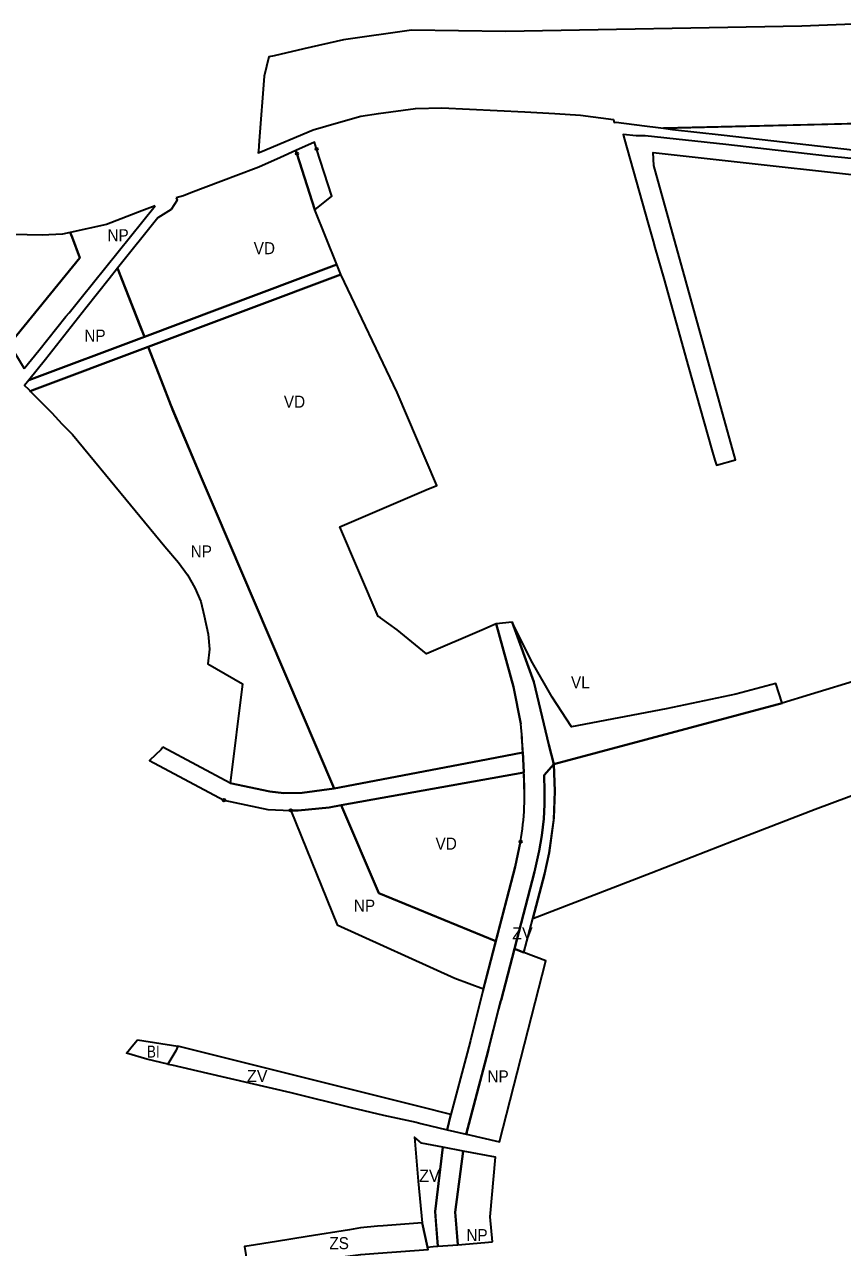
# Model space of a CAD drawing. Extents: x -650276 to -642489, y -1074311 to -1066658.
# Drawn here: x -649555 to -648741, y -1070383 to -1069166 of the extents above; entities that cross this region are included whole.
import ezdxf

# ---------------------------------------------------------------- set-up
doc = ezdxf.new("R2010")
doc.units = 0
doc.header["$LTSCALE"] = 4.8
doc.header["$PDMODE"] = 32
doc.header["$PDSIZE"] = 2.4
for name, color, linetype, lineweight in [('13', 7, 'Continuous', 35), ('15', 7, 'Continuous', 35), ('2', 7, 'Continuous', 35), ('24', 7, 'Continuous', 35), ('25', 7, 'Continuous', 35), ('35', 7, 'Continuous', 35), ('40', 7, 'Continuous', 35), ('41', 7, 'Continuous', 35), ('48', 7, 'Continuous', 35)]:
    doc.layers.add(name, color=color, linetype=linetype, lineweight=lineweight)
doc.layers.add('62', color=7, linetype='Continuous')

msp = doc.modelspace()

# ---------------------------------------------------------------- linework, layer by layer
at = {"layer": '13'}
msp.add_lwpolyline([(-648722.24, -1069817.54), (-648772.48, -1069832.83), (-648800.85, -1069841.52), (-649028.017, -1069902.109), (-649027.135, -1069928.902), (-649027.953, -1069955.702), (-649032.644, -1069990.371), (-649037.411, -1070011.659), (-649048.918, -1070055.852), (-648931.057, -1070010.171), (-648849.532, -1069978.559), (-648767.83, -1069946.87), (-648562.242, -1069870.301)], dxfattribs=at)
at = {"layer": '15'}
msp.add_line((-649057.868, -1069910.51), (-649058.82, -1069890.548), dxfattribs=at)
for points in [[(-648725.82, -1069299.81), (-648741.58, -1069298.16), (-648755.56, -1069296.7), (-648856.68, -1069285.01), (-648937.2, -1069276.37), (-648945.96, -1069276.64), (-648959.11, -1069275.13), (-648957.74, -1069280), (-648934.38, -1069362.79), (-648929.16, -1069381.32), (-648927.37, -1069387.62), (-648927.38, -1069387.623), (-648918.65, -1069418.53), (-648893.86, -1069506.89), (-648870.76, -1069589.26), (-648867.62, -1069599.37), (-648866.17, -1069604.48), (-648847.097, -1069598.995), (-648928.347, -1069306.125), (-648929.112, -1069293.123), (-648642.241, -1069324.949)], [(-649431.761, -1069486.57), (-649240.202, -1069414.528), (-649244.08, -1069404.753), (-649435.578, -1069476.772), (-649550.53, -1069519.68)], [(-649548.881, -1069530.963), (-649547.733, -1069530.185), (-649431.761, -1069486.57)], [(-649550.53, -1069519.68), (-649554.83, -1069525), (-649551.32, -1069528.49), (-649549.69, -1069530.14), (-649548.881, -1069530.963)], [(-649029.61, -1069835.47), (-649049.22, -1069801.23), (-649058.34, -1069783.72), (-649069.4, -1069760.67)], [(-649069.4, -1069760.67), (-649048, -1069820), (-649032.928, -1069882.782)], [(-649032.928, -1069882.782), (-649028.017, -1069902.109), (-648800.85, -1069841.52), (-648806.946, -1069821.79), (-648846.939, -1069832.584), (-648846.94, -1069832.584)], [(-648846.94, -1069832.584), (-648916.03, -1069847.12), (-649010.55, -1069865.09), (-649029.61, -1069835.47)], [(-649417.234, -1069885.193), (-649418.94, -1069887.36), (-649430.515, -1069898.514), (-649356.458, -1069937.945)], [(-649246.81, -1069926.27), (-649278.492, -1069930.573), (-649296.851, -1069931.092), (-649310.738, -1069929.342), (-649350.222, -1069920.873), (-649417.234, -1069885.193)], [(-649058.82, -1069890.548), (-649101.89, -1069898.73), (-649246.81, -1069926.27)], [(-649289.95, -1069948.146), (-649282.437, -1069948.342), (-649251.805, -1069945.276), (-649239.635, -1069943.094), (-649057.868, -1069910.51)], [(-649356.458, -1069937.945), (-649312.646, -1069947.342), (-649289.95, -1069948.146)]]:
    msp.add_lwpolyline(points, dxfattribs=at)
for p in [(-649356.458, -1069937.945), (-649289.95, -1069948.146)]:
    msp.add_point(p, dxfattribs=at)
at = {"layer": '2'}
msp.add_lwpolyline([(-649442.63, -1070176.69), (-649402.29, -1070182.92), (-649404.2, -1070187.43), (-649412.2, -1070200.71), (-649433.3, -1070195.89), (-649453.27, -1070190.02), (-649446.19, -1070180.76)], close=True, dxfattribs=at)
at = {"layer": '24'}
for p, q in [((-649283.702, -1069294.132), (-649265.774, -1069350.068)), ((-649058.858, -1069889.759), (-649057.868, -1069910.51)), ((-649057.134, -1069932.873), (-649057.868, -1069910.51)), ((-649146.163, -1070347.543), (-649145.424, -1070357.637))]:
    msp.add_line(p, q, dxfattribs=at)
for points in [[(-648721.315, -1069164.952), (-648781.015, -1069167.44), (-649076.02, -1069172.683), (-649169.781, -1069171.432), (-649237.512, -1069180.731), (-649277.021, -1069189.913), (-649306.455, -1069196.754), (-649311.633, -1069197.958), (-649316.47, -1069216.91), (-649321.32, -1069281.47), (-649322.09, -1069291.73), (-649322.22, -1069293.54), (-649319.72, -1069292.47), (-649267.5, -1069270.41), (-649242.5, -1069263.3), (-649220.18, -1069257.03), (-649202.63, -1069254.4), (-649165.62, -1069249.43), (-649139.63, -1069248.73), (-649056.95, -1069252.55), (-649026.955, -1069254.366), (-649001.3, -1069255.92), (-648968.49, -1069260.36), (-648968.05, -1069263.06), (-648965.8, -1069262.75), (-648937.91, -1069266.51), (-648924.13, -1069268.21), (-648918.889, -1069268.875), (-648673.267, -1069262.895)], [(-649264.156, -1069289.589), (-649266.331, -1069282.804), (-649284.695, -1069291.033), (-649283.702, -1069294.132)], [(-649265.774, -1069350.068), (-649249.069, -1069336.66), (-649264.156, -1069289.589)], [(-649061.138, -1069979.243), (-649061.138, -1069979.243), (-649061.139, -1069979.254), (-649066.487, -1070004.267), (-649098.65, -1070127.795), (-649110.925, -1070177.113), (-649114.174, -1070189.816), (-649130.712, -1070250.935), (-649134.294, -1070266.095), (-649115.159, -1070270.568), (-649095.152, -1070193.731), (-649093.095, -1070186.132), (-649095.152, -1070193.731), (-649080.924, -1070137.409), (-649080.38, -1070136.996), (-649047.131, -1070009.304), (-649042.468, -1069988.477), (-649042.468, -1069988.477), (-649039.966, -1069973.035), (-649037.98, -1069956.626), (-649037.322, -1069942.129), (-649037.137, -1069928.996), (-649037.665, -1069912.977), (-649028.017, -1069902.109), (-649032.928, -1069882.782), (-649048, -1069820), (-649069.4, -1069760.67), (-649085.41, -1069762.44), (-649068, -1069825.147), (-649060.897, -1069861.994)], [(-649138.43, -1070283.6), (-649146.163, -1070347.543), (-649146.163, -1070347.543), (-649145.424, -1070357.637)], [(-649125.503, -1070355.837), (-649126.069, -1070348.097), (-649118.257, -1070287.455), (-649138.43, -1070283.6), (-649146.163, -1070347.543)], [(-649125.503, -1070355.837), (-649126.069, -1070348.097), (-649118.257, -1070287.455), (-649138.43, -1070283.6)], [(-649145.424, -1070357.637), (-649143.633, -1070382.123), (-649123.693, -1070380.572), (-649125.503, -1070355.837)], [(-649145.424, -1070357.637), (-649143.633, -1070382.123), (-649123.693, -1070380.572), (-649125.503, -1070355.837)]]:
    msp.add_lwpolyline(points, dxfattribs=at)
for centre, radius, start, end in [((-649633.43, -1069918.001), 575.266, 2.81398, 5.58706), ((-649347.129, -1069931.193), 290, 350.46253, 4.08974), ((-649347.129, -1069931.193), 290, 359.66809, 4.08974)]:
    msp.add_arc(centre, radius, start, end, dxfattribs=at)
for p in [(-649264.156, -1069289.589), (-649283.702, -1069294.132)]:
    msp.add_point(p, dxfattribs=at)
at = {"layer": '25'}
msp.add_lwpolyline([(-648730.66, -1069290.43), (-648656.242, -1069297.116), (-648673.267, -1069262.895), (-648761.189, -1069265.035), (-648918.889, -1069268.875), (-648909.86, -1069270.02), (-648861.49, -1069275.34), (-648785.92, -1069284.2), (-648730.66, -1069290.43)], close=True, dxfattribs=at)
at = {"layer": '35'}
msp.add_line((-649202.375, -1070030.469), (-649085.737, -1070078.201), dxfattribs=at)
for points in [[(-649283.702, -1069294.132), (-649284.695, -1069291.033), (-649300.133, -1069297.95), (-649321.69, -1069307.61)], [(-649244.08, -1069404.753), (-649265.774, -1069350.068), (-649283.702, -1069294.132)], [(-649321.69, -1069307.61), (-649324.3, -1069308.59), (-649359.48, -1069321.82), (-649389.4, -1069333.35), (-649396.52, -1069336.09), (-649403.92, -1069338.26)], [(-649403.92, -1069338.26), (-649403.03, -1069340.66), (-649408.81, -1069349.89), (-649422.19, -1069357.99), (-649462.25, -1069408.32), (-649435.578, -1069476.772), (-649244.08, -1069404.753)], [(-649060.897, -1069861.994), (-649068, -1069825.147), (-649085.41, -1069762.44), (-649085.41, -1069762.44), (-649099.75, -1069768.575), (-649154.76, -1069792.11), (-649184.05, -1069768.45), (-649200.64, -1069756.53), (-649202.99, -1069754.99), (-649241.11, -1069665.9), (-649155.082, -1069629.097), (-649144.57, -1069624.6), (-649184.1, -1069532.2), (-649240.202, -1069414.528), (-649431.761, -1069486.57), (-649416.52, -1069525.68), (-649409.355, -1069544.517), (-649388.438, -1069594.296), (-649379.32, -1069615.71), (-649364.44, -1069650.55), (-649312.03, -1069773.33)], [(-649312.03, -1069773.33), (-649246.81, -1069926.27), (-649101.89, -1069898.73), (-649058.82, -1069890.548)], [(-649057.868, -1069910.51), (-649239.635, -1069943.094), (-649202.375, -1070030.469)], [(-649085.737, -1070078.201), (-649066.487, -1070004.267), (-649061.139, -1069979.254), (-649061.138, -1069979.243)]]:
    msp.add_lwpolyline(points, dxfattribs=at)
for centre, radius, start, end in [((-649649.71, -1069919.176), 591.583, 2.77379, 5.54687), ((-649347.129, -1069931.193), 290, 350.46253, 4.08974)]:
    msp.add_arc(centre, radius, start, end, dxfattribs=at)
msp.add_point((-649061.138, -1069979.243), dxfattribs=at)
at = {"layer": '40'}
for points in [[(-649060.411, -1070060.306), (-649067.061, -1070085.844), (-649057.722, -1070089.665), (-649048.918, -1070055.852), (-649037.411, -1070011.659), (-649032.644, -1069990.371), (-649028.007, -1069957.455), (-649027.135, -1069928.902), (-649028.017, -1069902.109), (-649037.665, -1069912.977), (-649037.137, -1069928.996), (-649037.322, -1069942.129), (-649037.98, -1069956.626), (-649039.966, -1069973.035), (-649042.468, -1069988.477), (-649047.131, -1070009.304)], [(-649160.748, -1070243.413), (-649402.29, -1070182.92), (-649404.2, -1070187.43), (-649412.2, -1070200.71), (-649412.2, -1070200.71), (-649408.24, -1070201.62), (-649372.69, -1070209.74), (-649289.83, -1070229.16), (-649229.8, -1070243.94), (-649197.55, -1070251.65), (-649164.91, -1070258.55), (-649160.54, -1070259.96), (-649134.294, -1070266.095), (-649130.712, -1070250.935)], [(-649138.43, -1070283.6), (-649159.78, -1070279.52), (-649166.86, -1070273.48), (-649162.91, -1070317.47), (-649159.19, -1070358.82), (-649153.64, -1070382.9), (-649148.23, -1070382.48), (-649143.633, -1070382.123), (-649146.163, -1070347.543)]]:
    msp.add_lwpolyline(points, close=True, dxfattribs=at)
at = {"layer": '41'}
msp.add_lwpolyline([(-649570.03, -1069483.83), (-649499.761, -1069397.905), (-649507.61, -1069377.35), (-649509.42, -1069372.61), (-649517.17, -1069374.3), (-649537.32, -1069375.23), (-649582.25, -1069374.51)], dxfattribs=at)
msp.add_lwpolyline([(-649159.19, -1070358.82), (-649197.91, -1070361.8), (-649203.4, -1070362.23), (-649220.47, -1070363.94), (-649231.39, -1070365.69), (-649273.57, -1070372.44), (-649304.18, -1070377.35), (-649331.3, -1070381.69), (-649335.79, -1070382.41), (-649332.2, -1070405.42), (-649294.79, -1070399.65), (-649269.769, -1070396.502), (-649220.16, -1070390.26), (-649202.969, -1070388.965), (-649153.11, -1070385.21), (-649153.64, -1070382.9)], close=True, dxfattribs=at)
at = {"layer": '48'}
for points in [[(-649555.16, -1069508.07), (-649540.81, -1069490.25), (-649513.66, -1069456.53), (-649510.56, -1069452.67), (-649498.47, -1069437.65), (-649424.8, -1069346.14)], [(-649424.8, -1069346.14), (-649438.17, -1069351.27), (-649473.35, -1069364.76), (-649473.35, -1069364.76), (-649509.42, -1069372.61), (-649507.61, -1069377.35), (-649499.761, -1069397.905)], [(-649499.761, -1069397.905), (-649570.03, -1069483.83), (-649555.16, -1069508.07)], [(-649493.94, -1069448.14), (-649534.06, -1069499.33), (-649550.53, -1069519.68), (-649435.578, -1069476.772), (-649440.466, -1069464.229), (-649462.25, -1069408.32)], [(-649462.25, -1069408.32), (-649470.71, -1069418.95), (-649493.94, -1069448.14), (-649493.94, -1069448.14)], [(-649114.172, -1070266.777), (-649114.931, -1070270.621), (-649082.233, -1070278.265), (-649036.031, -1070097.854), (-649057.722, -1070089.665), (-649067.061, -1070085.844)], [(-649067.061, -1070085.844), (-649080.38, -1070136.996), (-649080.872, -1070137.369), (-649083.108, -1070146.053)], [(-649083.108, -1070146.053), (-649095.152, -1070193.731), (-649093.095, -1070186.132), (-649095.152, -1070193.731), (-649114.172, -1070266.777)], [(-649089.07, -1070377.88), (-649091.46, -1070352.73), (-649086.157, -1070293.589), (-649118.257, -1070287.455), (-649126.069, -1070348.097)], [(-649126.069, -1070348.097), (-649123.693, -1070380.572), (-649089.07, -1070377.88)]]:
    msp.add_lwpolyline(points, dxfattribs=at)
for points in [[(-649392.85, -1069713.53), (-649385.25, -1069726.48), (-649379.49, -1069740.04), (-649376.01, -1069754.58), (-649372.2, -1069772.58), (-649370.94, -1069787.45), (-649372.56, -1069802.33), (-649372.56, -1069802.33), (-649338, -1069822), (-649350.222, -1069920.873), (-649310.738, -1069929.342), (-649296.851, -1069931.092), (-649278.492, -1069930.573), (-649246.81, -1069926.27), (-649312.03, -1069773.33), (-649364.44, -1069650.55), (-649379.32, -1069615.71), (-649407.002, -1069550.701), (-649416.52, -1069525.68), (-649431.761, -1069486.57), (-649547.733, -1069530.185), (-649548.881, -1069530.963), (-649538.49, -1069541.54), (-649527.84, -1069552.16), (-649517.81, -1069563.27), (-649507.23, -1069573.85), (-649474.46, -1069613.59), (-649415.12, -1069685.26), (-649401.77, -1069701.47)], [(-649251.805, -1069945.276), (-649282.437, -1069948.342), (-649289.95, -1069948.146), (-649243.846, -1070062.071), (-649126.437, -1070115.217), (-649126.437, -1070115.217), (-649098.101, -1070125.688), (-649085.737, -1070078.201), (-649202.375, -1070030.469), (-649239.635, -1069943.094)]]:
    msp.add_lwpolyline(points, close=True, dxfattribs=at)

# ---------------------------------------------------------------- texts
at = {"layer": '62'}
for s, width, p in [('NP', 0.95, (-649472.389, -1069381.42)), ('VD', 0.95, (-649326.761, -1069394.352)), ('NP', 0.95, (-649495.389, -1069481.42)), ('VD', 0.95, (-649296.767, -1069547.204)), ('NP', 0.95, (-649389.556, -1069696.287)), ('VL', 0.95, (-649010.928, -1069826.6)), ('VD', 0.95, (-649145.767, -1069987.204)), ('NP', 0.95, (-649227.076, -1070049.026)), ('BI', 0.85, (-649433.221, -1070194.292)), ('NP', 0.95, (-649094.076, -1070219.026)), ('NP', 0.95, (-649115.076, -1070377.026)), ('ZS', 0.95, (-649251.482, -1070385.05))]:
    msp.add_text(s, height=12, dxfattribs=dict(at, width=width)).set_placement(p)
for p in [(-649069.527, -1070076.528), (-649333.527, -1070218.528), (-649162.076, -1070318.026)]:
    msp.add_text('ZV', height=12, dxfattribs=at).set_placement(p)

doc.saveas('drawing.dxf')
